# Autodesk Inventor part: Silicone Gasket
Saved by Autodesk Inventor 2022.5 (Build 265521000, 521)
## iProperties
Created: 2025-02
Part Number: Silicone Gasket
Material: Generic
Document SubType Name: Modeling
Designer: AdminForWorker
Density: 1 g/cm^3
Appearance: Default
Title: Silicone Gasket
Author: AdminForWorker
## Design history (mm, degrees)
feature "Silicone Gasket"
body "Solid1"
